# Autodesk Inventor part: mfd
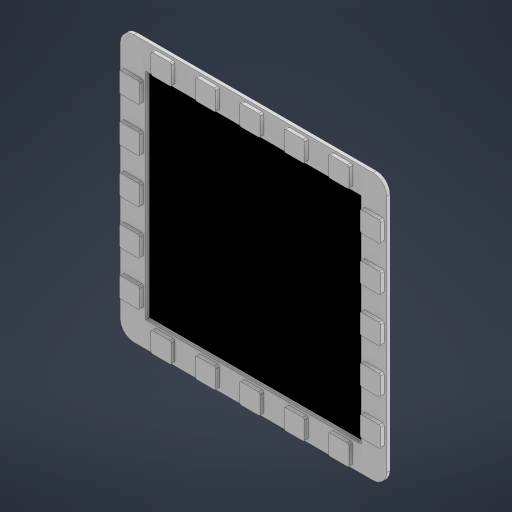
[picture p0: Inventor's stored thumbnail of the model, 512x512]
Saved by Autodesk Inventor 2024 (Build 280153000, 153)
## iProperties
Created: 2023-09
Part Number: mfd
Material: Generic
Document SubType Name: Modeling
Designer: mammothbane
Density: 1 g/cm^3
Appearance: Default
Author: mammothbane
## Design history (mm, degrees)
sketch "Sketch1"
  geometry: L1 (0, 0)-(-125.724, 0); L2 (-125.724, 0)-(-125.724, -125.724); L3 (-125.724, -125.724)-(0, -125.724); L4 (0, -125.724)-(0, 0); L5 (0, 0)-(-125.724, -125.724)
  constraints: 10 end point, 2 parallel, 2 perpendicular, 1 horizontal
  dimensions: "screen_diag" = 177.8 distance of L1.start L2.end
extrude "Extrusion1" new body sketch "Sketch1" distance "d1" = 3; taper "d2" = 0 deg
sketch "Sketch2"
  geometry: L1 (-125.724, 0)-(-125.724, -125.724) reference; L2 (-125.724, -125.724)-(0, -125.724) reference; L3 (0, -125.724)-(0, 0) reference; L4 (0, 0)-(-125.724, 0) reference; L5 (15, -140.724)-(-140.724, -140.724); L6 (-140.724, -140.724)-(-140.724, 15); L7 (-140.724, 15)-(15, 15); L8 (15, 15)-(15, -140.724)
  constraints: 8 end point, 3 other
  dimensions: "d4" = 15 distance between parallel lines of L2 L5 (= bezel_width)
extrude "Extrusion2" new body sketch "Sketch2" distance "d5" = 2; taper "d6" = 0 deg
sketch "Sketch3"
  geometry: L1 (6, 127.224)-(16, 127.224); L2 (17, 128.224)-(17, 138.224); L3 (16, 139.224)-(6, 139.224); L4 (5, 138.224)-(5, 128.224); L5 (5, 139.224)-(5, 140.724); L6 (140.724, 140.724)-(-15, 140.724) reference; L7 (5, 127.224)-(5, 125.724); L8 (0, 125.724)-(125.724, 125.724) reference; L9 (0, 0)-(0, 125.724) reference; A1 r 1 centre (6, 138.224) between (6, 139.224) and (5, 138.224); A2 r 1 centre (6, 128.224) between (5, 128.224) and (6, 127.224); A3 r 1 centre (16, 128.224) between (16, 127.224) and (17, 128.224); A4 r 1 centre (16, 138.224) between (17, 138.224) and (16, 139.224); 1 further point
  constraints: 12 end point, 9 point on line, 8 point on circle, 8 tangent, 4 centre point, 3 equal radius, 2 parallel, 1 collinear, 1 horizontal, 1 perpendicular, 1 vertical
  dimensions: "d7" = 12 distance of point (17, 139.224) L5.start (= button_width); "d8" = 12 distance between parallel lines of L1 L3 (= button_height); "d9" = 1 radius of A1 (= button_radius); "d11" = 5 distance between parallel lines of L9 L4 (= button_edge_padding)
extrude "Extrusion3" new body sketch "Sketch3" distance "d12" = 2; taper "d13" = 0 deg
pattern_linear "Rectangular Pattern1" dims "d16" = 25.9309 (= button_spacing)
workplane "Work Plane2"
workplane "Work Plane3"
mirror "Mirror2"
mirror "Mirror3"
fillet "Fillet1" dims "d17" = 8 (= bezel_radius)
body "Solid1"
node "Projected Loop1"
body "Solid2"
body "Solid3"
other parameters: "bezel_width" = 15 [user parameter; used in 2 equation terms], "button_height" = 12 (= 0.8 x bezel_width) [user parameter; used in 2 equation terms], "button_width" = 12 (= button_height) [user parameter; used in 2 equation terms], "button_radius" = 1 [user parameter; used in 1 equation term], "side_button_extents" = 103.72359 (= -2 x button_edge_padding + screen_width - button_width) [user parameter; used in 1 equation term], "button_spacing" = 25.9309 (computed from side_button_extents, buttons_per_side) [user parameter; used in 1 equation term], "screen_width" = 125.72359 (= 0.707107 x screen_diag) [user parameter; used in 1 equation term], "button_edge_padding" = 5 [user parameter; used in 2 equation terms], "bezel_radius" = 8 [user parameter; used in 1 equation term]
